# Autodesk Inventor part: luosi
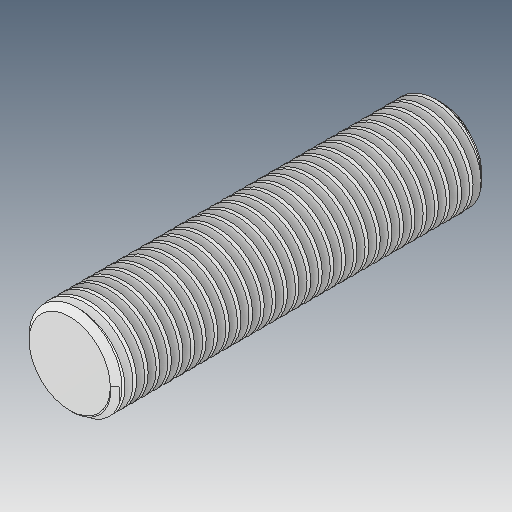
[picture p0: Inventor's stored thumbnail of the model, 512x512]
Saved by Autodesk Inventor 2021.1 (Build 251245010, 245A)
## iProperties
Created: 2021-06
Part Number: luosi
Material: Ogólny
Document SubType Name: Modeling
Designer: user
Density: 1 g/cm^3
Appearance: Domyślna
Author: user
Revision Number: ÈÎºÎ
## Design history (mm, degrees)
feature "ÇÐ³ý-É¨Ãè1"
node "Bryła1"
